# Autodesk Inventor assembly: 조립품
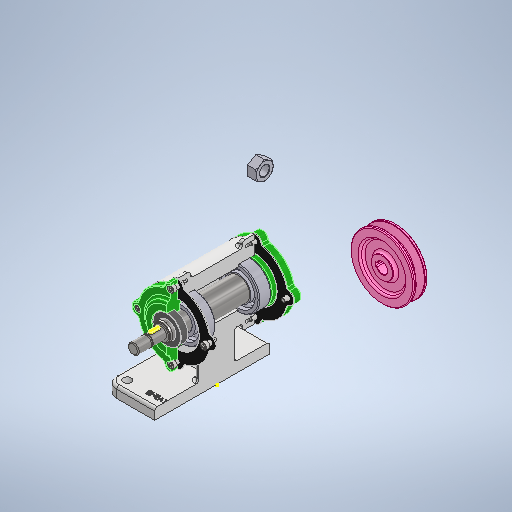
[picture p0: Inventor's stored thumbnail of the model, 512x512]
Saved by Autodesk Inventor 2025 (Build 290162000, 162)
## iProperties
Created: 2024-08
Part Number: 조립품
Document SubType Name: Assembly
Designer: SAMSUNG
Author: SAMSUNG
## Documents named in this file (13)
- C:\Users\SAMSUNG\Desktop\740807V1002\조립품.iam
- C:\Users\SAMSUNG\Desktop\740807V1002\본체.ipt
- C:\Users\SAMSUNG\Desktop\740807V1002\V-벨트풀리\V-벨트풀리.ipt
- C:\Users\SAMSUNG\Desktop\740807V1002\개스킷\개스킷.ipt
- C:\Users\SAMSUNG\Desktop\740807V1002\너트 M12 x 1.25\너트 M12 x 1.25.ipt
- C:\Users\SAMSUNG\Desktop\740807V1002\뒤커버\뒤커버.ipt
- C:\Users\SAMSUNG\Desktop\740807V1002\베어링 6204\베어링 6204.ipt
- C:\Users\SAMSUNG\Desktop\740807V1002\볼트 M4 x 12\볼트 M4 x 12.ipt
- C:\Users\SAMSUNG\Desktop\740807V1002\앞커버\앞커버.ipt
- C:\Users\SAMSUNG\Desktop\740807V1002\오일실\오일실.ipt
- C:\Users\SAMSUNG\Desktop\740807V1002\축\축.ipt
- C:\Users\SAMSUNG\Desktop\740807V1002\키 4 x 4\키 4 x 4.ipt
- C:\Users\SAMSUNG\Desktop\740807V1002\볼트 M4 x 12\볼트 M4 x 12_MIR.ipt
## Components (3 placed, 2 different names)
1. V-벨트풀리:1
2. 개스킷:1
3. 개스킷:2
